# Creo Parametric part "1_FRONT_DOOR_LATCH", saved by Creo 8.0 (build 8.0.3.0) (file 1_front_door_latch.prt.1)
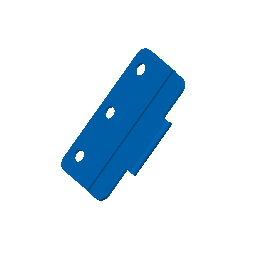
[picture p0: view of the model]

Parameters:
  SMT_DFLT_BEND_REL_LENGTH_TYPE = "Through All"

Other parameters: SMT_UPDATE_BEND_ALLOW_INFO, SMT_THICKNESS, SMT_PART_BEND_ALLOWANCE_FACTOR, SMT_DFLT_BEND_RADIUS, SMT_DFLT_BEND_ANGLE, SMT_DFLT_CRNR_REL_WIDTH, SMT_DFLT_CRNR_REL_DEPTH, SMT_DFLT_BEND_REL_WIDTH, SMT_DFLT_BEND_REL_DEPTH, SMT_DFLT_BEND_REL_LENGTH, SMT_DFLT_BEND_REL_ANGLE, SMT_GAP, SMT_DFLT_EDGE_TREA_WIDTH, SMT_DFLT_MITER_CUT_WIDTH, SMT_DFLT_MITER_CUT_OFFSET

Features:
  1. datum plane "RIGHT"
  2. datum plane "TOP"
  3. datum plane "FRONT"
  4. coordinate system
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
Layers: 0_ALL_AXIS, 0_ALL_CSYS, 0_ALL_CURVES, 0_ALL_PLANES, 0_ALL_POINTS, 0_ALL_SURFS, FRONT_DOOR_LATCH

Surfaces: 30 plane, 15 cylinder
